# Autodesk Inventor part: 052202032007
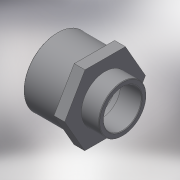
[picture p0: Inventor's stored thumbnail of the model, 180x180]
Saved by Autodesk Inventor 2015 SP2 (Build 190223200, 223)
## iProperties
Created: 2017-10
Part Number: 052202032007
Material: Generic
Description: PLASSON BUSHING ADAP. THR-CE 32(40)-3/4"
Document SubType Name: Modeling
Designer: KIM
Density: 1 g/cm^3
Appearance: Default
Author: KIM
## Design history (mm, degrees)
derived "052202.ipt"
feature "Solid1::052202.ipt"
tag "TaggingFeature1"
body "Solid1"
other parameters: "d0" = 59, "d2" = 46, "d13" = 0, "d14" = 0.32, "d17" = 26, "d18" = 20.4, "d20" = 32, "d21" = 26.441, "d22" = 22, "d23" = 30.4, "d24" = 21.1528, "d25" = 17, "d26" = -26, "d_" = 32, "R_" = 26.441, "C_" = 46, "B_" = 12, "L_" = 26, "lt_" = 17, "H_" = 59, "l_" = 22
